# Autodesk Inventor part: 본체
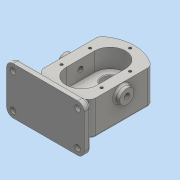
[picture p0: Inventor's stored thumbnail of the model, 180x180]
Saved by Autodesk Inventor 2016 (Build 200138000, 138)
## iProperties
Created: 2019-03
Part Number: 본체
Material: 일반
Document SubType Name: Modeling
Designer: 3sil_cad0123
Density: 1 g/cm^3
Appearance: 기본값
Author: 3sil_cad0123
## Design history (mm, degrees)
sketch "스케치1"
  geometry: L1 (-40, 60)-(40, 60); L2 (40, 60)-(40, 0); L3 (40, 0)-(-40, 0); L4 (-40, 0)-(-40, 60); L5 (0, 60)-(0, 0); A1 r 60 centre (0, 0) between (40, 44.721) and (-40, 44.721); 1 further point
  constraints: 10 end point, 2 coincident, 2 midpoint, 2 parallel, 2 point on circle, 2 point on line, 1 centre point, 1 horizontal, 1 perpendicular
  dimensions: "d0" = 80 distance of L1.start L1.end; "d1" = 60 distance of L3.end L1.start; "d2" = 120 diameter of A1
extrude "돌출1" new body sketch "스케치1" stored distance "d3" = 53; taper "d4" = 0 deg
sketch "스케치2"
  geometry: L1 (-24, -22)-(24, -22); L2 (24, -22)-(24, 22); L3 (24, 22)-(-24, 22); L4 (-24, 22)-(-24, -22); L5 (-24, -22)-(24, 22); L6 (24, -22)-(-24, 22); C1 r 24 at (0, 22); C2 r 24 at (0, -22); A1 r 60 centre (0, 0) between (40, 44.721) and (-40, 44.721) reference; A2 r 60 centre (0, 0) between (-40, -44.721) and (40, -44.721) reference; 1 further point
  constraints: 12 end point, 4 midpoint, 2 centre point, 2 parallel, 1 coincident, 1 horizontal, 1 perpendicular
  dimensions: "d5" = 48 diameter of C1; "d6" = 48 distance of L2.end L3.end; "d7" = 22 vertical distance of A1.centre L2.end; "d8" = 48 diameter of C2
extrude "돌출2" cut sketch "스케치2" distance "d9" = 29; taper "d10" = 0 deg
sketch "스케치3"
  geometry: L1 (0, 0)-(0, -89.443) reference; C1 r 11 at (14, -44.721); 1 further point
  constraints: 1 centre point, 1 horizontal alignment
  dimensions: "d11" = 22 diameter of C1; "d12" = 14 distance from line of L1 C1.centre
extrude "돌출3" join sketch "스케치3" distance "d13" = 8; taper "d14" = 0 deg
sketch "스케치4"
  geometry: L1 (53, 0)-(53, -89.443) reference; C1 r 11 at (39, -44.721); 1 further point
  constraints: 1 centre point, 1 horizontal alignment
  dimensions: "d15" = 22 diameter of C1; "d16" = 14 distance from line of L1 C1.centre
extrude "돌출4" join sketch "스케치4" distance "d17" = 8; taper "d18" = 0 deg
sketch "스케치5"
  geometry: C1 r 11 at (0, 0) reference; 1 further point
hole "구멍1" sketch "스케치5" at (0, 0) diameter "d19" = 8.376; stored, may be unused: countersink angle "d23" = 90 deg, drill point angle "d25" = 0 deg; dims "d20" = 100, "d21" = 4, "d22" = 2, "d24" = 27.3
sketch "스케치6"
  geometry: C1 r 12.5 at (0, 22); C2 r 12.5 at (0, -22); A1 r 24 centre (0, 22) between (24, 22) and (-24, 22) reference; A2 r 24 centre (0, -22) between (-24, -22) and (24, -22) reference; 1 further point
  constraints: 2 centre point, 2 coincident
  dimensions: "d26" = 25 diameter of C1; "d27" = 25 diameter of C2
extrude "돌출5" cut sketch "스케치6" distance "d28" = 15; taper "d29" = 0 deg
sketch "스케치9"
  geometry: L1 (-31, -22)-(31, -22); L2 (31, -22)-(31, 22); L3 (31, 22)-(-31, 22); L4 (-31, 22)-(-31, -22); L5 (-31, -22)-(31, 22); L6 (31, -22)-(-31, 22); A1 r 24 centre (0, 22) between (24, 22) and (-24, 22) reference; A2 r 24 centre (0, -22) between (-24, -22) and (24, -22) reference; A3 r 60 centre (0, 0) between (-40, -44.721) and (40, -44.721) reference; A4 r 31 centre (0, 22) between (0, 53) and (-31, 22); A5 r 31 centre (0, -22) between (0, -53) and (31, -22); 2 further points
  constraints: 12 end point, 4 coincident, 4 point on circle, 2 centre point, 2 midpoint, 2 parallel, 1 horizontal, 1 perpendicular, 1 point on line
  dimensions: "d39" = 44 distance of L1.end L2.end; "d40" = 62 distance of L2.end L3.end; "d41" = 62 diameter of A4; "d42" = 62 diameter of A5
hole "구멍2" sketch "스케치9" at (0, 53), (-31, 22), (-31, -22), (0, -53), (31, -22), (31, 22) diameter "d43" = 4.134; stored, may be unused: countersink angle "d47" = 90 deg, drill point angle "d49" = 118 deg; dims "d44" = 10, "d45" = 4, "d46" = 2, "d48" = 12
sketch "스케치11"
  geometry: L1 (-60, -78)-(60, -78); L2 (60, -78)-(60, -68); L3 (60, -68)-(-60, -68); L4 (-60, -68)-(-60, -78); L5 (-60, -78)-(60, -68); L6 (60, -78)-(-60, -68); A1 r 60 centre (0, 0) between (40, 44.721) and (-40, 44.721) reference; 2 further points
  constraints: 12 end point, 3 midpoint, 2 parallel, 1 horizontal, 1 perpendicular, 1 vertical alignment
  dimensions: "d53" = 10 distance of L1.end L2.end; "d54" = 120 distance of L1.start L1.end; "d55" = 78 distance from line of A1.centre L1
extrude "돌출9" join sketch "스케치11" distance "d56" = 73; taper "d57" = 0 deg
sketch "스케치12"
  geometry: L1 (0, 0)-(120, 0) reference; L2 (54, -43)-(66, -43); L3 (66, -43)-(66, 0); L4 (66, 0)-(54, 0); L5 (54, 0)-(54, -43); L6 (54, -43)-(66, 0); L7 (66, -43)-(54, 0); 3 further points
  constraints: 12 end point, 3 midpoint, 2 parallel, 1 horizontal, 1 perpendicular, 1 point on line, 1 vertical alignment
  dimensions: "d58" = 12 distance of L2.start L2.end; "d59" = 43 distance of L2.end L3.end
extrude "돌출10" join sketch "스케치12" stored distance "d60" = 73; taper "d61" = 0 deg
fillet "모깎기1" dims "d62" = 10
sketch "스케치13"
  geometry: A1 r 10 centre (56, -20) between (56, -30) and (66, -20) reference; A2 r 10 centre (56, 33) between (66, 33) and (56, 43) reference; A3 r 10 centre (-44, 33) between (-44, 43) and (-54, 33) reference; A4 r 10 centre (-44, -20) between (-54, -20) and (-44, -30) reference; 1 further point
hole "구멍3" sketch "스케치13" at (-44, 33), (-44, -20), (56, -20), (56, 33) diameter "d63" = 9; stored, may be unused: countersink angle "d67" = 90 deg, drill point angle "d69" = 0 deg; dims "d64" = 10, "d65" = 4, "d66" = 2, "d68" = 12
sketch "스케치14"
  geometry: C1 r 12.5 at (0, 22) reference; C2 r 19 at (0, 22)
  constraints: 1 centre point, 1 coincident
  dimensions: "d76" = 38 diameter of C2
extrude "돌출11" join sketch "스케치14" distance "d77" = 17; taper "d78" = 0 deg
sketch "스케치15"
  geometry: C1 r 12.5 at (0, 0) reference; C2 r 8.5 at (0, 0); 1 further point
  constraints: 1 centre point, 1 coincident
  dimensions: "d79" = 17 diameter of C2
extrude "돌출12" cut sketch "스케치15" stored distance "d80" = 17; taper "d81" = 0 deg
sketch "스케치16"
  geometry: C1 r 19 at (0, 0) reference; C2 r 14 at (0, 0); 1 further point
  constraints: 1 centre point, 1 coincident
  dimensions: "d82" = 28 diameter of C2
extrude "돌출13" cut sketch "스케치16" distance "d83" = 7.3; taper "d84" = 0 deg
chamfer "모따기3" distance "d85" = 0.7; stored, may be unused: second distance "d86" = 2, angle "d87" = 30 deg
fillet "모깎기2" dims "d88" = 0.5
fillet "모깎기3" dims "d89" = 3
fillet "모깎기4" dims "d90" = 10
chamfer "모따기4" distance "d91" = 1; stored, may be unused: second distance "d92" = 2, angle "d93" = 30 deg
node "작업 평면1"
sketch "스케치17"
  geometry: L1 (0, -3)-(100, -3) reference; L2 (-10, 60)-(-10, 7) reference; 2 further points
  constraints: 1 other
  dimensions: "d95" = 10 distance from line of L1 point (50, 7); "d96" = 60 distance from line of L2 point (50, 7)
feature "엠보싱1" sketch "스케치17" dims "d0" = 80, "d1" = 60, "d2" = 120, "d5" = 48, "d6" = 48, "d7" = 22, "d8" = 48, "d97" = 0.5, "d98" = 0
fillet "모깎기5" dims "d99" = 3
node "솔리드1"
mirror "대칭1"
other parameters: "d94" = 51.75
